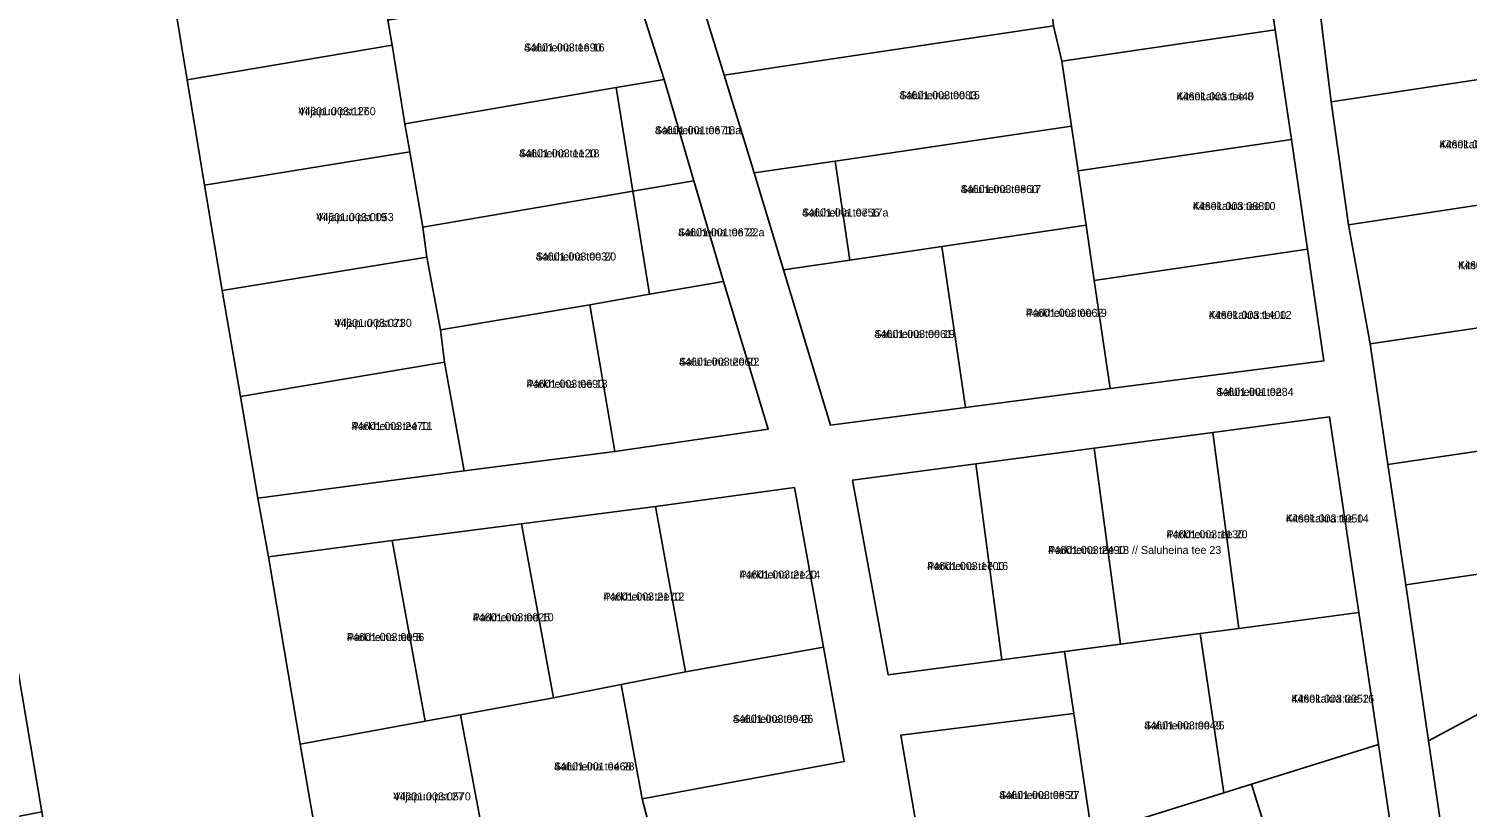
# Model space of a CAD drawing. Extents: x 551843 to 558501, y 6589003 to 6595718.
# Drawn here: x 553189.3 to 553458.8, y 6593652.3 to 6593798.2 of the extents above; entities that cross this region are included whole.
import ezdxf

# ---------------------------------------------------------------- set-up
doc = ezdxf.new("R2010")
doc.units = 0
for name, color, linetype in [('L_AADRESS', 7, 'Continuous'), ('PIIR', 7, 'Continuous'), ('TUNNUS', 7, 'Continuous')]:
    doc.layers.add(name, color=color, linetype=linetype)

msp = doc.modelspace()

# ---------------------------------------------------------------- linework, layer by layer
at = {"layer": 'PIIR'}
for points in [[(553186.23, 6593983.27), (553193.49, 6593939.32), (553196.91, 6593918.08), (553200.54, 6593897.24), (553204.15, 6593876.28), (553210.71, 6593836.66), (553212.49, 6593828.12), (553215.73, 6593808.36), (553218.98, 6593788.61), (553222.26, 6593768.87), (553225.56, 6593749.13), (553229, 6593729.26), (553232.23, 6593710.23), (553234.24, 6593699.21), (553240.17, 6593664.09), (553244.79, 6593637.48), (553249.21, 6593611.32), (553254.67, 6593579.06), (553203.23, 6593583.33), (553196.77, 6593621.59), (553191.73, 6593651.42), (553186.62, 6593681.71)], [(553313.97, 6593807.78), (553319.6, 6593789.52), (553325.24, 6593771.22), (553330.7, 6593752.99), (553339.51, 6593723.89), (553364.83, 6593727.2), (553391.92, 6593730.74), (553431.99, 6593735.97), (553428.92, 6593756.87), (553425.88, 6593777.44), (553422.84, 6593798.01), (553419.8, 6593818.58)], [(553305.63, 6593648.61), (553304.26, 6593653.85), (553342.12, 6593660.8), (553338.22, 6593682.29), (553332.79, 6593712.2), (553306.75, 6593708.65), (553281.62, 6593705.41), (553257.38, 6593702.24), (553234.24, 6593699.21), (553232.23, 6593710.23), (553270.9, 6593715.3), (553299.14, 6593718.94), (553327.86, 6593723.11), (553319.47, 6593750.85), (553313.92, 6593769.72), (553308.34, 6593788.7), (553302.37, 6593807.5)], [(553430.62, 6593806.89), (553433.32, 6593784.52), (553436.6, 6593761.45), (553440.63, 6593739.12), (553443.97, 6593716.53), (553447.31, 6593693.94), (553451.6, 6593664.73), (553456.92, 6593628.62)], [(553447.86, 6593626.29), (553442.22, 6593664.03), (553438.54, 6593688.77), (553433.05, 6593725.43), (553411.17, 6593722.52), (553388.96, 6593719.59), (553366.76, 6593716.65), (553343.65, 6593713.57), (553350.34, 6593677.06), (553371.63, 6593679.88), (553383.4, 6593681.45), (553385.14, 6593669.82), (553352.71, 6593665.77), (553357.52, 6593637.75)]]:
    msp.add_lwpolyline(points, dxfattribs=at)
for points in [[(553419.8, 6593818.58), (553422.84, 6593798.01), (553382.88, 6593792.14), (553381.34, 6593798.78), (553379.84, 6593812.71)], [(553215.73, 6593808.36), (553254.14, 6593814.87), (553256.61, 6593799.83), (553257.39, 6593795.12), (553218.98, 6593788.61)], [(553379.84, 6593812.71), (553381.34, 6593798.78), (553337.4, 6593792.19), (553319.6, 6593789.52), (553313.97, 6593807.78), (553333.81, 6593810.69), (553334.52, 6593810.74), (553356.3, 6593814.04), (553379.19, 6593817.12)], [(553430.62, 6593806.89), (553467.23, 6593812.98), (553468.8, 6593801.92), (553470.45, 6593790.14), (553433.32, 6593784.52)], [(553299.34, 6593787.17), (553259.8, 6593780.39), (553257.39, 6593795.12), (553256.61, 6593799.83), (553278.38, 6593803.5), (553302.37, 6593807.5), (553308.34, 6593788.7)], [(553325.24, 6593771.22), (553319.6, 6593789.52), (553337.4, 6593792.19), (553381.34, 6593798.78), (553382.88, 6593792.14), (553384.68, 6593779.96), (553340.43, 6593773.41)], [(553425.88, 6593777.44), (553385.92, 6593771.57), (553384.68, 6593779.96), (553382.88, 6593792.14), (553422.84, 6593798.01)], [(553218.98, 6593788.61), (553257.39, 6593795.12), (553259.8, 6593780.39), (553260.71, 6593775.15), (553222.26, 6593768.87)], [(553299.34, 6593787.17), (553308.34, 6593788.7), (553313.92, 6593769.72), (553302.49, 6593767.76)], [(553470.45, 6593790.14), (553472.74, 6593775.77), (553474.02, 6593767.15), (553436.6, 6593761.45), (553433.32, 6593784.52)], [(553263.16, 6593761.02), (553260.71, 6593775.15), (553259.8, 6593780.39), (553299.34, 6593787.17), (553302.49, 6593767.76)], [(553340.43, 6593773.41), (553384.68, 6593779.96), (553385.92, 6593771.57), (553387.42, 6593761.38), (553360.38, 6593757.38), (553343.17, 6593754.83)], [(553428.92, 6593756.87), (553388.95, 6593751), (553387.42, 6593761.38), (553385.92, 6593771.57), (553425.88, 6593777.44)], [(553222.26, 6593768.87), (553260.71, 6593775.15), (553263.16, 6593761.02), (553263.89, 6593755.38), (553225.56, 6593749.13)], [(553343.17, 6593754.83), (553330.7, 6593752.99), (553325.24, 6593771.22), (553340.43, 6593773.41)], [(553305.62, 6593748.44), (553302.49, 6593767.76), (553313.92, 6593769.72), (553319.47, 6593750.85)], [(553263.89, 6593755.38), (553263.16, 6593761.02), (553302.49, 6593767.76), (553305.62, 6593748.44), (553294.44, 6593746.48), (553266.48, 6593741.75)], [(553436.6, 6593761.45), (553474.02, 6593767.15), (553476.25, 6593752.53), (553477.43, 6593744.57), (553440.63, 6593739.12)], [(553364.83, 6593727.2), (553360.38, 6593757.38), (553387.42, 6593761.38), (553388.95, 6593751), (553391.92, 6593730.74)], [(553339.51, 6593723.89), (553330.7, 6593752.99), (553343.17, 6593754.83), (553360.38, 6593757.38), (553364.83, 6593727.2)], [(553391.92, 6593730.74), (553388.95, 6593751), (553428.92, 6593756.87), (553431.99, 6593735.97)], [(553229, 6593729.26), (553225.56, 6593749.13), (553263.89, 6593755.38), (553266.48, 6593741.75), (553267.2, 6593735.73)], [(553305.62, 6593748.44), (553319.47, 6593750.85), (553327.86, 6593723.11), (553299.14, 6593718.94), (553294.44, 6593746.48)], [(553266.48, 6593741.75), (553294.44, 6593746.48), (553299.14, 6593718.94), (553270.9, 6593715.3), (553267.2, 6593735.73)], [(553443.97, 6593716.53), (553440.63, 6593739.12), (553477.43, 6593744.57), (553480.21, 6593723.58), (553480.76, 6593721.97)], [(553232.23, 6593710.23), (553229, 6593729.26), (553267.2, 6593735.73), (553270.9, 6593715.3)], [(553433.05, 6593725.43), (553438.54, 6593688.77), (553416.04, 6593685.78), (553411.17, 6593722.52)], [(553411.17, 6593722.52), (553416.04, 6593685.78), (553408.79, 6593684.81), (553393.84, 6593682.83), (553388.96, 6593719.59)], [(553443.97, 6593716.53), (553480.76, 6593721.97), (553483.66, 6593702.32), (553484.1, 6593699.37), (553447.31, 6593693.94)], [(553366.76, 6593716.65), (553388.96, 6593719.59), (553393.84, 6593682.83), (553371.63, 6593679.88)], [(553366.76, 6593716.65), (553371.63, 6593679.88), (553350.34, 6593677.06), (553343.65, 6593713.57)], [(553332.79, 6593712.2), (553338.22, 6593682.29), (553312.38, 6593677.67), (553306.75, 6593708.65)], [(553306.75, 6593708.65), (553312.38, 6593677.67), (553300.33, 6593675.29), (553287.6, 6593672.78), (553281.62, 6593705.41)], [(553281.62, 6593705.41), (553287.6, 6593672.78), (553270.23, 6593669.6), (553263.58, 6593668.38), (553257.38, 6593702.24)], [(553257.38, 6593702.24), (553263.58, 6593668.38), (553240.17, 6593664.09), (553234.24, 6593699.21)], [(553484.1, 6593699.37), (553486.46, 6593683.41), (553467.99, 6593673.52), (553451.6, 6593664.73), (553447.31, 6593693.94)], [(553442.22, 6593664.03), (553418.42, 6593656.57), (553413.24, 6593654.95), (553408.79, 6593684.81), (553416.04, 6593685.78), (553438.54, 6593688.77)], [(553393.84, 6593682.83), (553408.79, 6593684.81), (553413.24, 6593654.95), (553397.41, 6593649.99), (553388.52, 6593647.21), (553385.14, 6593669.82), (553383.4, 6593681.45)], [(553158.12, 6593675.89), (553186.62, 6593681.71), (553191.73, 6593651.42), (553152.34, 6593643.76), (553147.42, 6593673.71)], [(553312.38, 6593677.67), (553338.22, 6593682.29), (553342.12, 6593660.8), (553304.26, 6593653.85), (553300.33, 6593675.29)], [(553270.23, 6593669.6), (553287.6, 6593672.78), (553300.33, 6593675.29), (553304.26, 6593653.85), (553305.63, 6593648.61), (553275.22, 6593643.04)], [(553456.92, 6593628.62), (553451.6, 6593664.73), (553467.99, 6593673.52), (553484.19, 6593643.24)], [(553240.17, 6593664.09), (553263.58, 6593668.38), (553270.23, 6593669.6), (553275.22, 6593643.04), (553244.79, 6593637.48)], [(553352.71, 6593665.77), (553385.14, 6593669.82), (553388.52, 6593647.21), (553376.39, 6593643.42), (553357.52, 6593637.75)], [(553442.22, 6593664.03), (553447.86, 6593626.29), (553429.68, 6593620.59), (553418.42, 6593656.57)], [(553408.67, 6593614.02), (553397.41, 6593649.99), (553413.24, 6593654.95), (553418.42, 6593656.57), (553429.68, 6593620.59)]]:
    msp.add_lwpolyline(points, close=True, dxfattribs=at)

# ---------------------------------------------------------------- texts
at = {"layer": 'L_AADRESS'}
for s, p in [('Saluheina tee 16', (553282.13, 6593793.95)), ('Saluheina tee 15', (553352.46, 6593785)), ('Kitsekakra tee 8', (553404.38, 6593784.79)), ('Viljapuu pst 17', (553239.81, 6593782)), ('Saluheina tee 18a', (553306.63, 6593778.44)), ('Kitsekakra tee 7', (553453.65, 6593775.79)), ('Saluheina tee 18', (553281.18, 6593774.1)), ('Saluheina tee 17', (553363.93, 6593767.4)), ('Viljapuu pst 19', (553243.18, 6593762.14)), ('Saluheina tee 17a', (553334.21, 6593763.01)), ('Kitsekakra tee 10', (553407.42, 6593764.22)), ('Saluheina tee 22a', (553310.98, 6593759.29)), ('Saluheina tee 20', (553284.3, 6593754.76)), ('Kitsekakra tee 9', (553457.13, 6593753.13)), ('Parkheina tee 19', (553376.15, 6593744.2)), ('Kitsekakra tee 12', (553410.42, 6593743.8)), ('Viljapuu pst 21', (553246.56, 6593742.32)), ('Saluheina tee 19', (553347.77, 6593740.24)), ('Saluheina tee 22', (553311.15, 6593735.04)), ('Parkheina tee 13', (553282.59, 6593730.89)), ('Saluheina tee', (553411.81, 6593729.38)), ('Parkheina tee 11', (553249.79, 6593722.98)), ('Kitsekakra tee 14', (553424.86, 6593705.65)), ('Parkheina tee 20', (553402.5, 6593702.68)), ('Parkheina tee 18 // Saluheina tee 23', (553380.3, 6593699.74)), ('Parkheina tee 14', (553322.48, 6593695.14)), ('Parkheina tee 16', (553357.64, 6593696.73)), ('Parkheina tee 12', (553297, 6593691.01)), ('Parkheina tee 10', (553272.49, 6593687.11)), ('Parkheina tee 8', (553248.91, 6593683.41)), ('Kitsekakra tee 16', (553425.89, 6593671.86)), ('Saluheina tee 26', (553321.23, 6593668.07)), ('Saluheina tee 25', (553398.32, 6593666.85)), ('Saluheina tee 28', (553287.74, 6593659.16)), ('Viljapuu pst 27', (553257.62, 6593653.54)), ('Saluheina tee 27', (553371.15, 6593653.79))]:
    msp.add_text(s, height=1.5, dxfattribs=at).set_placement(p)
at = {"layer": 'TUNNUS'}
for s, p in [('44601:003:1690', (553282.13, 6593793.95)), ('44601:003:0083', (553352.46, 6593785)), ('44601:003:1440', (553404.38, 6593784.79)), ('44601:003:1260', (553239.81, 6593782)), ('44601:001:0671', (553306.63, 6593778.44)), ('44601:003:2070', (553453.65, 6593775.79)), ('44601:003:1120', (553281.18, 6593774.1)), ('44601:003:0860', (553363.93, 6593767.4)), ('44601:003:0053', (553243.18, 6593762.14)), ('44601:001:0756', (553334.21, 6593763.01)), ('44601:003:0880', (553407.42, 6593764.22)), ('44601:001:0672', (553310.98, 6593759.29)), ('44601:003:0037', (553284.3, 6593754.76)), ('44601:003:0890', (553457.13, 6593753.13)), ('44601:003:0062', (553376.15, 6593744.2)), ('44601:003:1400', (553410.42, 6593743.8)), ('44601:003:0730', (553246.56, 6593742.32)), ('44601:003:0061', (553347.77, 6593740.24)), ('44601:003:2060', (553311.15, 6593735.04)), ('44601:003:0690', (553282.59, 6593730.89)), ('44601:001:0284', (553411.81, 6593729.38)), ('44601:003:2470', (553249.79, 6593722.98)), ('44601:003:1050', (553424.86, 6593705.65)), ('44601:003:1130', (553402.5, 6593702.68)), ('44601:003:2490', (553380.3, 6593699.74)), ('44601:003:2120', (553322.48, 6593695.14)), ('44601:003:1700', (553357.64, 6593696.73)), ('44601:003:2170', (553297, 6593691.01)), ('44601:003:0025', (553272.49, 6593687.11)), ('44601:003:0056', (553248.91, 6593683.41)), ('44601:003:0052', (553425.89, 6593671.86)), ('44601:003:0048', (553321.23, 6593668.07)), ('44601:003:0049', (553398.32, 6593666.85)), ('44601:001:0468', (553287.74, 6593659.16)), ('44601:003:0570', (553257.62, 6593653.54)), ('44601:003:0850', (553371.15, 6593653.79))]:
    msp.add_text(s, height=1.5, dxfattribs=at).set_placement(p)

doc.saveas('drawing.dxf')
